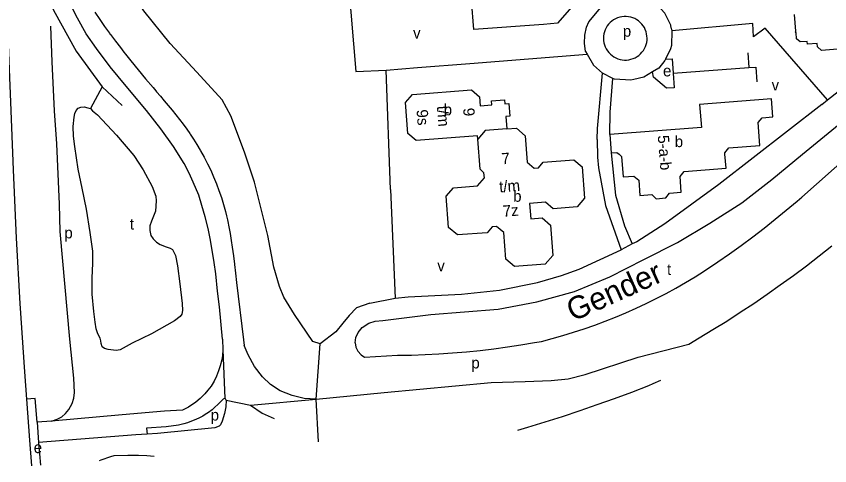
# Model space of a CAD drawing. Extents: x 157794 to 159375, y 380877 to 382306.
# Drawn here: x 157944 to 158233.2, y 380889.2 to 381049.1 of the extents above; entities that cross this region are included whole.
import ezdxf

# ---------------------------------------------------------------- set-up
doc = ezdxf.new("R2010")
doc.units = 0
for name, color, linetype in [('BLT_Basislijn', 7, 'Continuous'), ('BLT_Bebouwing', 7, 'Continuous'), ('BLT_Centroide', 7, 'Continuous'), ('BLT_Huisnummer_reeks', 7, 'Continuous'), ('BLT_Onderverdeling_panden', 7, 'Continuous'), ('BLT_Vlakafsluiter', 7, 'Continuous'), ('BLT_Waternaam_spoorwegen', 7, 'Continuous')]:
    doc.layers.add(name, color=color, linetype=linetype)

msp = doc.modelspace()

# ---------------------------------------------------------------- linework, layer by layer
at = {"layer": 'BLT_Basislijn'}
for p, q in [((158176.86, 381044.92), (158177.08, 381043.96)), ((158105.19, 381032.28), (158146.98, 381035.61)), ((158204.06, 381036.14), (158204.41, 381030.84)), ((158177.48, 381028.85), (158204.41, 381030.84)), ((158077.06, 380987.5), (158075.51, 381029.92)), ((158156.12, 381027.04), (158152.43, 381028.87)), ((158232.42, 381019.42), (158243.03, 381027.77)), ((157974.51, 381024.02), (157970.35, 381016.29)), ((157974.51, 381024.02), (157981.6, 381017.32)), ((158230.32, 381017.77), (158232.42, 381019.42)), ((158223.28, 380984.81), (158244.77, 381003.83)), ((158077.06, 380987.5), (158078.63, 380948.8)), ((158162.93, 380968.12), (158159.04, 380965.96)), ((158069.71, 380947.02), (158078.63, 380948.8)), ((158017.24, 380934.18), (158017.4, 380930.48)), ((157956.49, 380905.11), (157951.34, 380904.7)), ((157951.34, 380904.7), (157951.91, 380897.46)), ((157951.91, 380897.46), (157952.53, 380889.43))]:
    msp.add_line(p, q, dxfattribs=at)
for points in [[(158055.79, 381166.34), (158053.25, 381166.13), (158064.63, 381029.51)], [(157934.65, 381160.68), (157935.7, 381144.42), (157936.49, 381134.3), (157937.03, 381125.41), (157937.84, 381112.36), (157938.63, 381097.02), (157939.91, 381066.83), (157940.97, 381042.02), (157941.87, 381018.61), (157942.89, 380994.44), (157943.91, 380970.19), (157945.28, 380946.87), (157946.92, 380922.55), (157947.64, 380912.88)], [(158146.39, 381036.63), (158146.02, 381039.6), (158146.08, 381042.39), (158146.66, 381045.27), (158147.55, 381047.09), (158153.02, 381053.61), (158154.88, 381057.84), (158155.01, 381064.16), (158153.31, 381085.39), (158153.51, 381086.58)], [(158052.05, 380932.59), (158049.41, 380933.42), (158042.83, 380943.01), (158039.05, 380949.16), (158037.6, 380952.96), (158035.52, 380959.89), (158033.42, 380971.12), (158028.68, 380990.05), (158025.05, 381000.76), (158020.21, 381013.7), (158017.15, 381019.44), (158008.21, 381029.22), (157998.71, 381039.46), (157989.31, 381051.01), (157982.79, 381061.35), (157973.65, 381078.85)], [(157950.1, 381069.92), (157953.72, 381059.06), (157957.14, 381051.29), (157965.28, 381036.75), (157974.51, 381024.02)], [(158017.24, 380934.18), (158016.26, 380945.71), (158015.56, 380951.31), (158014.9, 380957.53), (158014.29, 380961.55), (158012.98, 380969.48), (158012.16, 380973.56), (158011.16, 380977.77), (158009.98, 380981.76), (158008.87, 380985.41), (158006.86, 380990.14), (158005.41, 380993.34), (158003.6, 380996.76), (157999.88, 381002.75), (157995.33, 381009.1), (157990.25, 381015.55), (157983.03, 381024.26), (157977.37, 381031.08), (157972.45, 381037.64), (157968.85, 381042.93), (157965.73, 381048.44), (157962.67, 381054.47), (157959.76, 381060.71), (157955.82, 381069.77)], [(158176.86, 381044.92), (158176.64, 381045.97), (158174.54, 381050.2), (158169.18, 381056.11), (158166.74, 381060.33), (158165.82, 381069.75)], [(157971.9, 381050.57), (157973.61, 381048.03), (157975.37, 381045.53), (157977.13, 381043.09), (157977.16, 381043.05), (157977.42, 381042.7), (157977.46, 381042.65), (157979.18, 381040.32), (157980.97, 381037.96), (157982.2, 381036.38), (157982.8, 381035.62), (157984.66, 381033.29), (157987.27, 381030.09), (157989.91, 381026.9), (157992.58, 381023.72), (157993.55, 381022.58), (157993.83, 381022.25), (157995.21, 381020.64), (157996.59, 381019.02), (157997.97, 381017.39), (157999.34, 381015.73), (158000.7, 381014.05), (158002.01, 381012.39), (158003.3, 381010.7), (158004.56, 381008.98), (158005.64, 381007.44), (158005.79, 381007.22), (158007.01, 381005.38), (158008.19, 381003.51), (158009.38, 381001.5), (158009.51, 381001.26), (158010.77, 380998.98), (158011.96, 380996.67), (158013.09, 380994.32), (158014.14, 380991.94), (158015.12, 380989.52), (158016.03, 380987.08), (158016.87, 380984.62), (158017.64, 380982.13), (158018.33, 380979.62), (158018.7, 380978.15), (158019.04, 380976.68), (158019.18, 380976.07), (158019.56, 380974.24), (158020.01, 380971.8), (158020.4, 380969.37), (158020.75, 380966.94), (158021.15, 380963.84), (158021.5, 380960.9), (158021.52, 380960.75), (158021.86, 380957.68), (158022.22, 380954.43), (158024.77, 380933.98), (158024.99, 380932)], [(158168.25, 381041.3), (158168.21, 381042.09), (158168.09, 381042.87), (158167.89, 381043.63), (158167.61, 381044.37), (158167.27, 381045.07), (158166.85, 381045.74), (158166.37, 381046.36), (158165.82, 381046.93), (158165.23, 381047.45), (158164.58, 381047.9), (158163.89, 381048.28), (158163.16, 381048.58), (158162.41, 381048.82), (158161.64, 381048.97), (158160.86, 381049.05), (158160.07, 381049.05), (158159.29, 381048.97), (158158.51, 381048.8), (158157.76, 381048.57), (158157.04, 381048.25), (158156.35, 381047.87), (158155.71, 381047.41), (158155.12, 381046.9), (158154.58, 381046.32), (158154.1, 381045.7), (158153.68, 381045.03), (158153.34, 381044.32), (158153.07, 381043.58), (158152.88, 381042.82), (158152.77, 381042.04), (158152.73, 381041.25), (158152.78, 381040.46), (158152.9, 381039.69), (158153.1, 381038.93), (158153.38, 381038.19), (158153.74, 381037.48), (158154.16, 381036.82), (158154.64, 381036.2), (158155.19, 381035.63), (158155.79, 381035.13), (158156.44, 381034.68), (158157.14, 381034.31), (158157.86, 381034), (158158.62, 381033.77), (158159.39, 381033.62), (158160.17, 381033.55), (158160.96, 381033.56), (158161.74, 381033.65), (158162.51, 381033.81), (158163.26, 381034.06), (158163.98, 381034.38), (158164.67, 381034.77), (158165.31, 381035.22), (158165.9, 381035.74), (158166.43, 381036.32), (158166.91, 381036.95), (158167.32, 381037.62), (158167.65, 381038.33), (158167.92, 381039.08), (158168.11, 381039.84), (158168.22, 381040.62), (158168.25, 381041.3)], [(157956.49, 380905.11), (157958.47, 380905.71), (157960.16, 380906.65), (157961.52, 380907.77), (157962.67, 380909.22), (157963.82, 380911.37), (157964.39, 380913.21), (157964.69, 380915.27), (157964.39, 380920.36), (157963.06, 380934.22), (157959.54, 380972.49), (157959.27, 380982.31), (157958.41, 381003.76), (157957.58, 381015.43), (157956.74, 381032.92), (157956.28, 381045.65)], [(158232.42, 381019.42), (158210.17, 381044.95), (158206.06, 381041.78), (158205.81, 381046.52), (158177.08, 381043.96)], [(158177.08, 381043.96), (158176.89, 381038.72), (158176.57, 381037.54), (158174.75, 381033.81)], [(158146.39, 381036.63), (158146.98, 381035.61)], [(158146.98, 381035.61), (158149.21, 381031.74), (158152.43, 381028.87)], [(158174.75, 381033.81), (158174.52, 381033.34), (158172.36, 381030.71), (158170.19, 381029.36)], [(158174.75, 381033.81), (158177.12, 381034), (158177.48, 381028.85)], [(158075.51, 381029.92), (158086.65, 381030.85), (158105.19, 381032.28)], [(158204.41, 381030.84), (158206.88, 381031.02), (158207.22, 381025.77)], [(158064.63, 381029.51), (158075.51, 381029.92)], [(158150.54, 381005.32), (158150.56, 381009.15), (158152.43, 381028.87)], [(158170.19, 381029.36), (158167.09, 381027.42), (158163.53, 381026.59), (158162.48, 381026.41), (158156.71, 381026.74), (158156.12, 381027.04)], [(158177.48, 381028.85), (158177.84, 381023.69), (158175.15, 381023.5), (158170.47, 381027.48), (158170.19, 381029.36)], [(158154.95, 381007), (158155.08, 381014.98), (158156.12, 381027.04)], [(157970.35, 381016.29), (157971.03, 381015.48), (157972.78, 381014.11), (157979.55, 381006.78), (157985.7, 380999.6), (157989.09, 380994.48), (157992.24, 380988.57), (157993.52, 380985.1), (157993.7, 380983.43), (157993.43, 380979.74), (157991.99, 380976.27), (157991.5, 380974.5), (157991.5, 380972.91), (157991.83, 380971.13), (157992.6, 380969.92), (157993.87, 380968.71), (157995.13, 380967.91), (157997.26, 380967.09), (157998.7, 380966.65), (157999.52, 380966.12), (158000.54, 380964.03), (158001.32, 380960.35), (158002.15, 380953.9), (158003, 380946.92), (158003.03, 380944.48), (158002.77, 380943.11), (158002.2, 380942.24), (158000.17, 380940.75), (157992.05, 380936.18), (157985.12, 380932.84), (157980.93, 380930.41), (157979.5, 380930.23), (157976.68, 380930.53), (157975.31, 380930.91), (157974.54, 380931.48), (157974.09, 380932.66), (157974.08, 380933.66), (157973.77, 380934.61), (157972.9, 380936.13), (157972.31, 380937.96), (157971.97, 380940.27), (157971.51, 380944.06), (157970.94, 380950.29), (157970.99, 380955.88), (157971.21, 380961.24), (157971.17, 380965.6), (157970.27, 380972.23), (157968.9, 380980.49), (157967.36, 380988.01), (157965.99, 380994.72), (157964.78, 381002.79), (157964.34, 381006.52), (157964.24, 381009.89), (157964.49, 381013.19), (157964.74, 381014.52), (157965.25, 381015.63), (157965.99, 381016.39), (157966.96, 381016.77), (157968.12, 381016.89), (157969.43, 381016.6), (157970.35, 381016.29)], [(158230.32, 381017.77), (158193.72, 380989.23), (158174.6, 380975.28), (158164.58, 380968.91), (158162.93, 380968.12)], [(158064.43, 380932.98), (158064.69, 380934.78), (158065.51, 380936.63), (158066.96, 380938.41), (158069.31, 380939.98), (158071.61, 380940.69), (158074.3, 380940.88), (158091.41, 380942.98), (158115.31, 380944.89), (158129.02, 380947.53), (158142.49, 380951.19), (158155.01, 380956.42), (158167.09, 380962.6), (158179.03, 380968.68), (158190.58, 380975.48), (158201.94, 380982.78), (158212.62, 380991.04), (158223.5, 381000), (158237.86, 381011.81)], [(158150.54, 381005.32), (158150.61, 380998.96), (158150.99, 380995.22), (158153.43, 380981.74), (158159.04, 380965.96)], [(158155.46, 381000.51), (158157, 380985.42), (158160.18, 380974.6), (158162.93, 380968.12)], [(158188.65, 380958.51), (158193.43, 380961.71), (158197.6, 380964.61), (158201.73, 380967.58), (158205.8, 380970.61), (158209.83, 380973.71), (158213.81, 380976.87), (158217.74, 380980.09), (158221.62, 380983.37), (158223.28, 380984.81)], [(158050.61, 380912.9), (158074.74, 380915.2), (158112.79, 380918.78), (158124.93, 380919.15), (158134.14, 380919.47), (158140.24, 380920.17), (158146.26, 380921.62), (158165.03, 380927.86), (158183.06, 380932.49), (158186.76, 380934.65), (158191.67, 380937.63), (158196.55, 380940.67), (158201.38, 380943.79), (158206.17, 380946.97), (158210.91, 380950.21), (158215.61, 380953.52), (158220.26, 380956.9), (158224.87, 380960.34), (158229.42, 380963.85), (158233.93, 380967.41)], [(158078.63, 380948.8), (158083.26, 380949.32), (158102.27, 380950.2), (158115.73, 380951.71), (158129.26, 380954.42), (158137.82, 380956.93), (158144.05, 380959.17), (158159.04, 380965.96)], [(158130.69, 380933.43), (158134.53, 380934.44), (158138.34, 380935.52), (158142.13, 380936.68), (158145.9, 380937.92), (158149.64, 380939.24), (158153.35, 380940.62), (158157.03, 380942.09), (158160.68, 380943.62), (158164.31, 380945.24), (158167.9, 380946.92), (158171.45, 380948.68), (158174.97, 380950.5), (158178.45, 380952.4), (158181.89, 380954.37), (158185.29, 380956.41), (158188.65, 380958.51)], [(158069.71, 380947.02), (158064.91, 380945.36), (158062.36, 380942.62), (158060.09, 380939.97), (158057.54, 380936.85), (158052.05, 380932.59)], [(158064.43, 380932.98), (158064.69, 380931.36), (158065.38, 380929.93), (158066.57, 380928.68), (158067.76, 380927.79), (158079.54, 380928.5), (158084.43, 380928.59), (158089.33, 380928.76), (158094.21, 380929.01), (158099.1, 380929.34), (158103.98, 380929.75), (158108.85, 380930.24), (158113.71, 380930.8), (158118.56, 380931.45), (158123.4, 380932.18), (158128.23, 380932.99), (158130.69, 380933.43)], [(158017.4, 380930.48), (158017.24, 380928.46), (158017.01, 380926.84), (158016.49, 380924.78), (158015.89, 380922.92), (158015.19, 380921.05), (158014.33, 380919.23), (158013.29, 380917.56), (158012.08, 380916.05), (158010.95, 380914.76), (158009.33, 380913.12), (158007.77, 380911.76), (158005.22, 380910.09), (158003.04, 380909.01), (157996.67, 380908.58), (157981.58, 380907.34), (157956.49, 380905.11)], [(158050.61, 380912.9), (158046.35, 380913.14), (158042.05, 380914.13), (158037.82, 380915.89), (158034.38, 380918.12), (158031.48, 380920.81), (158028.7, 380924.49), (158026.36, 380928.62), (158024.99, 380932)], [(158122.28, 380901.86), (158125.79, 380902.89), (158132.01, 380904.78), (158138.21, 380906.76), (158144.39, 380908.81), (158150.54, 380910.93), (158156.66, 380913.14), (158162.76, 380915.41), (158168.83, 380917.76), (158170.44, 380918.4)], [(158170.44, 380918.4), (158173.18, 380919.64)], [(157951.34, 380904.7), (157950.63, 380913.13), (157947.64, 380912.88)], [(157947.64, 380912.88), (157948.72, 380898.33), (157949.42, 380889.19)], [(158018.06, 380913.06), (158017.8, 380913), (158017.55, 380912.88), (158017.39, 380912.75), (158016.6, 380911.91), (158015.65, 380910.95), (158014.6, 380909.98), (158013.59, 380909.11), (158012.32, 380908.18), (158011.13, 380907.37), (158010.26, 380906.83), (158009.1, 380906.21), (158007.85, 380905.63), (158006.31, 380905.01), (158004.83, 380904.47), (158003.57, 380904.06), (158001.67, 380903.61), (157997.22, 380903.08), (157990.26, 380902.54), (157990.45, 380900.39)], [(158018.59, 380912.57), (158018.46, 380910.19), (158018.01, 380907.75), (158017.15, 380905.09), (158016.61, 380903.77), (158016.04, 380903.22), (158014.59, 380902.66), (157994.14, 380900.64), (157990.45, 380900.39)], [(158018.59, 380912.57), (158018.51, 380912.81), (158018.36, 380912.98), (158018.06, 380913.06)], [(158027.29, 380910.77), (158031.33, 380907.95), (158035.62, 380906.03)], [(157990.45, 380900.39), (157986.47, 380900.13), (157951.91, 380897.46)], [(157973.5, 380891.09), (157974.09, 380891.31), (157977.56, 380892.52), (157978.71, 380892.88), (157983.65, 380892.97), (157987.46, 380892.94), (157990.39, 380892.79), (157992.99, 380892.63)]]:
    msp.add_lwpolyline(points, dxfattribs=at)
at = {"layer": 'BLT_Bebouwing'}
msp.add_line((158154.95, 381007), (158155.46, 381000.51), dxfattribs=at)
for points in [[(158143.27, 381091.16), (158145.81, 381057.52), (158136.44, 381046.62), (158131.46, 381046.24), (158106.65, 381044.38), (158105.86, 381054.88), (158077.17, 381052.71)], [(158221.39, 381041.12), (158221.23, 381043.24), (158221, 381043.59), (158221.11, 381043.83), (158220.66, 381049.81)], [(158242.27, 381037.88), (158236.46, 381037.44), (158236.24, 381037.19), (158235.89, 381037.36), (158230.26, 381036.94), (158228.79, 381038.21), (158228.7, 381039.41), (158225.29, 381039.15), (158225.21, 381040.18), (158222.7, 381039.99), (158221.39, 381041.12)], [(158108.03, 381005.38), (158107.94, 381006.62), (158086.08, 381004.9), (158083.18, 381007.37), (158082.32, 381018.4), (158084.8, 381021.28), (158105.77, 381022.94), (158108.66, 381020.46), (158108.91, 381017.23), (158113.09, 381017.61), (158112.98, 381019.03), (158117.52, 381019.37), (158117.63, 381017.94), (158119.07, 381018.03), (158119.42, 381013.52), (158118.01, 381013.42), (158118.33, 381009.05)], [(158155.46, 381000.51), (158157.51, 381000.67), (158158.29, 381000.01), (158159.15, 380999.27), (158159.73, 380991.95), (158163.57, 380992.25), (158165.25, 380990.81), (158165.68, 380985.31), (158169.93, 380985.65), (158171.47, 380984.2), (158174.91, 380984.48), (158176.22, 380986.15), (158180.4, 380986.48), (158179.96, 380992.13), (158181.44, 380993.86), (158196.34, 380995.04), (158195.94, 381000), (158195.89, 381000.59), (158197.32, 381002.27), (158208.33, 381003.14), (158207.68, 381011.32), (158209.12, 381013), (158212.97, 381013.31), (158212.46, 381019.79), (158186.93, 381017.77), (158187.58, 381009.57), (158154.95, 381007)], [(158118.33, 381009.05), (158121.76, 381009.32), (158124.92, 381006.61), (158125.64, 380997.2), (158128.1, 380995.09), (158129.6, 380995.21), (158131.29, 380997.18), (158142.25, 380998.02), (158145.16, 380995.53), (158146.01, 380984.42), (158143.35, 380981.32), (158134.86, 380980.66), (158132.15, 380982.98), (158126.45, 380982.54), (158126.87, 380977.06), (158130.89, 380977.36), (158133.92, 380974.77), (158134.74, 380964.04), (158132.05, 380960.89), (158121.09, 380960.05), (158117.97, 380962.72), (158117.25, 380972.13), (158114.67, 380974.34), (158113.19, 380974.23), (158111.38, 380972.11), (158100.81, 380971.3), (158097.64, 380974.02), (158096.79, 380985.09), (158099.36, 380988.1), (158107.95, 380988.76), (158110.39, 380991.61), (158110.25, 380993.47), (158108.86, 380994.66), (158108.03, 381005.38)]]:
    msp.add_lwpolyline(points, dxfattribs=at)
at = {"layer": 'BLT_Onderverdeling_panden'}
msp.add_lwpolyline([(158118.33, 381009.05), (158110.68, 381008.47), (158108.03, 381005.38)], dxfattribs=at)
at = {"layer": 'BLT_Vlakafsluiter'}
for p, q in [((158050.61, 380912.9), (158052.05, 380932.59)), ((158017.4, 380930.48), (158018.06, 380913.06)), ((158018.59, 380912.57), (158027.29, 380910.77)), ((158027.29, 380910.77), (158050.61, 380912.9)), ((158051.41, 380897.7), (158050.61, 380912.9))]:
    msp.add_line(p, q, dxfattribs=at)

# ---------------------------------------------------------------- texts
at = {"layer": 'BLT_Centroide'}
for s, p in [('p', (158159.62, 381041.85)), ('v', (158085.03, 381041.18)), ('e', (158173.9, 381027.73)), ('v', (158212.5, 381022.72)), ('b', (158095.94, 381013.91)), ('b', (158178.08, 381002.56)), ('b', (158120.63, 380983.12)), ('t', (157984.31, 380973.23)), ('p', (157961.06, 380970.09)), ('v', (158093.66, 380958.39)), ('t', (158175.33, 380957.06)), ('p', (158105.75, 380923.81)), ('p', (158013.07, 380905.27)), ('e', (157950.17, 380893.69))]:
    msp.add_text(s, height=4, dxfattribs=at).set_placement(p)
at = {"layer": 'BLT_Huisnummer_reeks'}
for s, rotation, p in [('t/m', 274.4172, (158093.53, 381017.14)), ('9', 274.4772, (158102.82, 381016.37)), ('9s', 274.4172, (158086.26, 381015.8)), ('5-a-b', 274.5246, (158172.01, 381006.66)), ('7', 4.3978, (158116.62, 380996.41)), ('t/m', 4.3908, (158115.8, 380986.44)), ('7z', 4.3908, (158117.07, 380977.77))]:
    msp.add_text(s, height=4, rotation=rotation, dxfattribs=at).set_placement(p)
at = {"layer": 'BLT_Waternaam_spoorwegen'}
msp.add_text('Gender', height=8, rotation=24.2296, dxfattribs=at).set_placement((158141.88, 380940.39))

doc.saveas('drawing.dxf')
